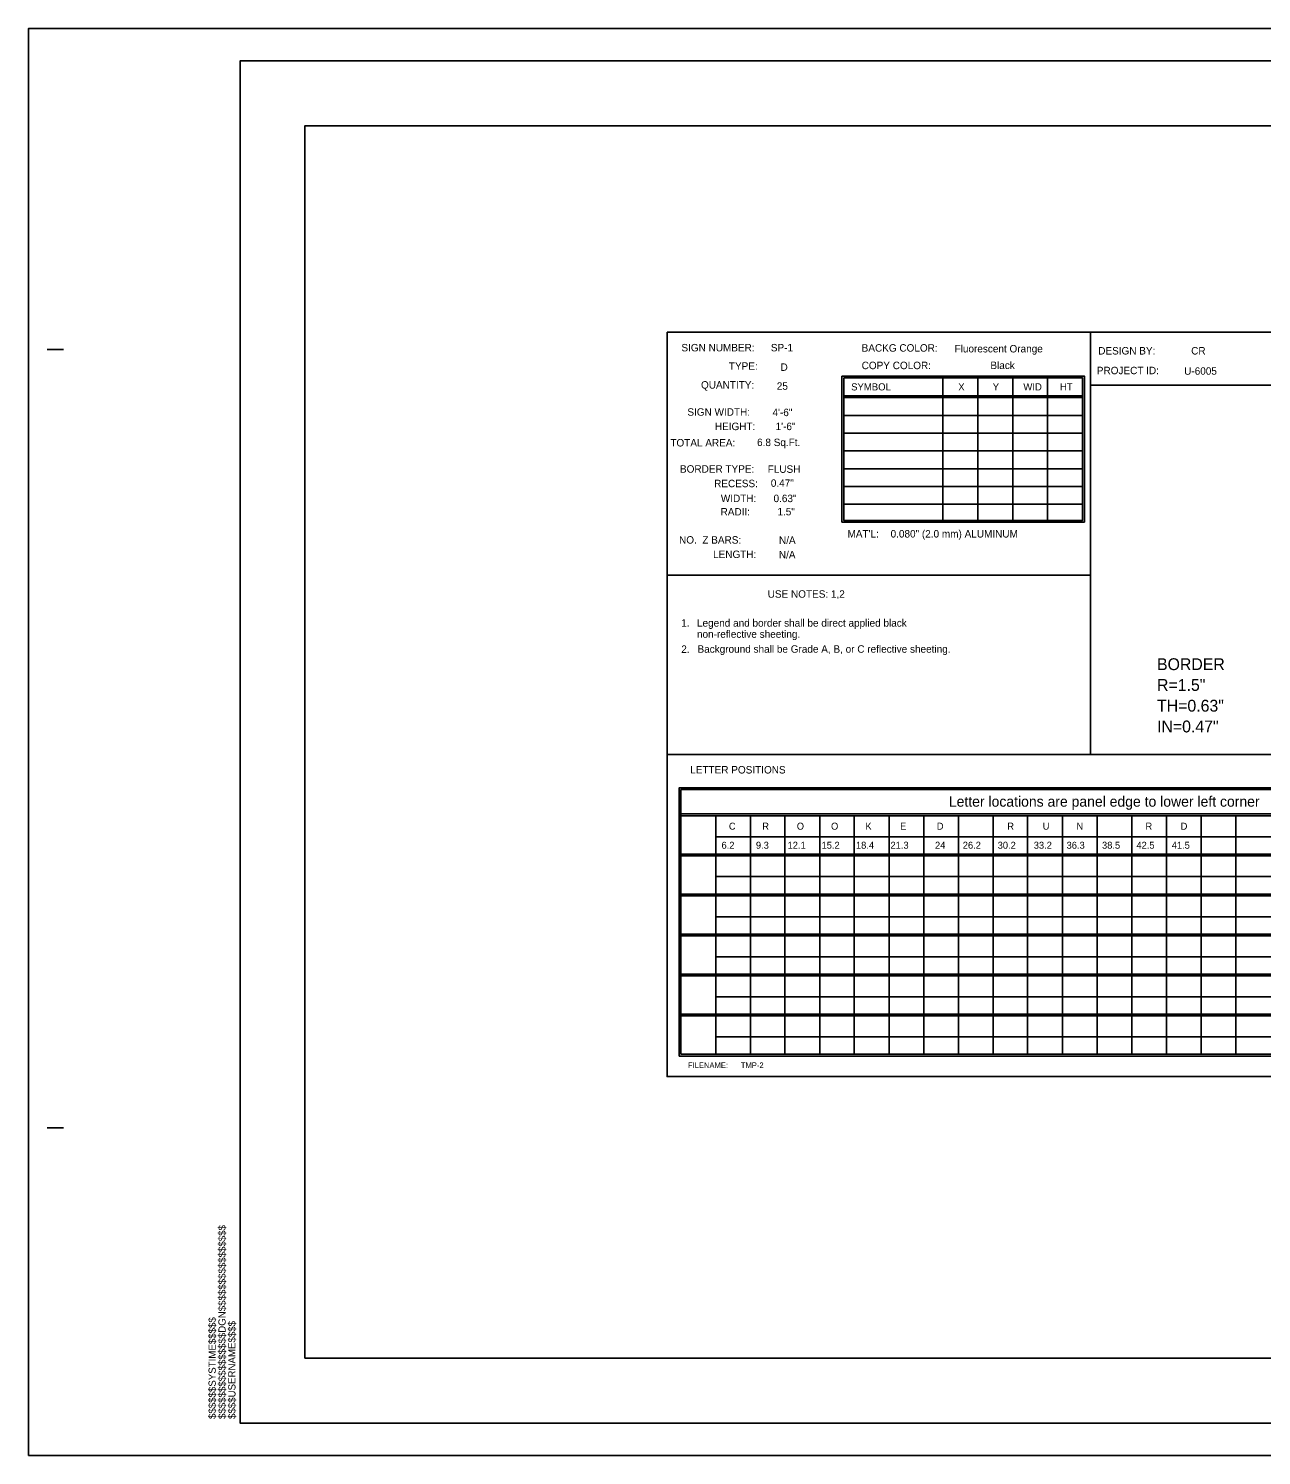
# Model space of a CAD drawing. Extents: x 768137 to 769825, y 651421 to 652521.
# Drawn here: x 768137 to 769087, y 651421 to 652521 of the extents above; entities that cross this region are included whole.
import ezdxf

# ---------------------------------------------------------------- set-up
doc = ezdxf.new("R2010")
doc.units = 0
for name, color, linetype in [('DEV BORDER CELL', 7, 'Continuous'), ('Old_Level_3', 7, 'Continuous'), ('Scratch_Level_0', 7, 'Continuous'), ('Sheet Plot Border Outside CELL', 7, 'Continuous'), ('Text', 7, 'Continuous')]:
    doc.layers.add(name, color=color, linetype=linetype)

msp = doc.modelspace()

# ---------------------------------------------------------------- linework, layer by layer
at = {"layer": 'DEV BORDER CELL'}
for p, q in [((768151.8, 652273.8), (768164.3, 652273.8)), ((768151.8, 651673.8), (768164.3, 651673.8))]:
    msp.add_line(p, q, dxfattribs=at)
msp.add_lwpolyline([(769800.3, 652496.3), (768300.3, 652496.3), (768300.3, 651446.3), (769800.3, 651446.3)], close=True, dxfattribs=at)
at = {"layer": 'Scratch_Level_0'}
msp.add_lwpolyline([(769750.3, 652446.3), (768350.3, 652446.3), (768350.3, 651496.3), (769229.2, 651496.3), (769229.2, 651614.6), (769750.3, 651614.6)], close=True, dxfattribs=at)
at = {"layer": 'Sheet Plot Border Outside CELL'}
msp.add_lwpolyline([(768137.3, 651421.3), (769825.3, 651421.3), (769825.3, 652521.3), (768137.3, 652521.3)], close=True, dxfattribs=at)
at = {"layer": 'Text'}
for p, q in [((768955.5, 652287.3), (768955.5, 651961.7)), ((768841.9, 652251.9), (768841.9, 652142.1)), ((768868.8, 652251.9), (768868.8, 652142.1)), ((768895.7, 652251.9), (768895.7, 652142.1)), ((768922.6, 652251.9), (768922.6, 652142.1)), ((768955.5, 652246.4), (769457, 652246.4)), ((768765.5, 652238.2), (768949.5, 652238.2)), ((768765.5, 652236.9), (768949.5, 652236.9)), ((768765.5, 652223.1), (768949.5, 652223.1)), ((768765.5, 652209.4), (768949.5, 652209.4)), ((768765.5, 652195.7), (768949.5, 652195.7)), ((768765.5, 652181.9), (768949.5, 652181.9)), ((768765.5, 652168.2), (768949.5, 652168.2)), ((768765.5, 652154.5), (768949.5, 652154.5)), ((768955.5, 652099.8), (768629.3, 652099.8)), ((768629.3, 651961.7), (768955.5, 651961.7)), ((768955.5, 651961.7), (769457, 651961.7)), ((768640, 651915.8), (769276.3, 651915.8)), ((768640, 651914.4), (769276.3, 651914.4)), ((768666.8, 651914.4), (768666.8, 651884.9)), ((768693.6, 651914.4), (768693.6, 651884.9)), ((768720.2, 651914.4), (768720.2, 651884.9)), ((768747, 651914.4), (768747, 651884.9)), ((768773.6, 651914.4), (768773.6, 651884.9)), ((768800.4, 651914.4), (768800.4, 651884.9)), ((768827.2, 651914.4), (768827.2, 651884.9)), ((768853.8, 651914.4), (768853.8, 651884.9)), ((768880.6, 651914.4), (768880.6, 651884.9)), ((768907.2, 651914.4), (768907.2, 651884.9)), ((768934, 651914.4), (768934, 651884.9)), ((768960.8, 651914.4), (768960.8, 651884.9)), ((768987.4, 651914.4), (768987.4, 651884.9)), ((769014.2, 651914.4), (769014.2, 651884.9)), ((769040.8, 651914.4), (769040.8, 651884.9)), ((769067.6, 651914.4), (769067.6, 651884.9)), ((768666.8, 651898.3), (769276.3, 651898.3)), ((768640, 651884.9), (769276.3, 651884.9)), ((768640, 651883.6), (769276.3, 651883.6)), ((768666.8, 651883.6), (768666.8, 651854.1)), ((768693.6, 651883.6), (768693.6, 651854.1)), ((768720.2, 651883.6), (768720.2, 651854.1)), ((768747, 651883.6), (768747, 651854.1)), ((768773.6, 651883.6), (768773.6, 651854.1)), ((768800.4, 651883.6), (768800.4, 651854.1)), ((768827.2, 651883.6), (768827.2, 651854.1)), ((768853.8, 651883.6), (768853.8, 651854.1)), ((768880.6, 651883.6), (768880.6, 651854.1)), ((768907.2, 651883.6), (768907.2, 651854.1)), ((768934, 651883.6), (768934, 651854.1)), ((768960.8, 651883.6), (768960.8, 651854.1)), ((768987.4, 651883.6), (768987.4, 651854.1)), ((769014.2, 651883.6), (769014.2, 651854.1)), ((769040.8, 651883.6), (769040.8, 651854.1)), ((769067.6, 651883.6), (769067.6, 651854.1)), ((768666.8, 651867.5), (769276.3, 651867.5)), ((768640, 651854.1), (769276.3, 651854.1)), ((768640, 651852.7), (769276.3, 651852.7)), ((768666.8, 651852.7), (768666.8, 651823.2)), ((768693.6, 651852.7), (768693.6, 651823.2)), ((768720.2, 651852.7), (768720.2, 651823.2)), ((768747, 651852.7), (768747, 651823.2)), ((768773.6, 651852.7), (768773.6, 651823.2)), ((768800.4, 651852.7), (768800.4, 651823.2)), ((768827.2, 651852.7), (768827.2, 651823.2)), ((768853.8, 651852.7), (768853.8, 651823.2)), ((768880.6, 651852.7), (768880.6, 651823.2)), ((768907.2, 651852.7), (768907.2, 651823.2)), ((768934, 651852.7), (768934, 651823.2)), ((768960.8, 651852.7), (768960.8, 651823.2)), ((768987.4, 651852.7), (768987.4, 651823.2)), ((769014.2, 651852.7), (769014.2, 651823.2)), ((769040.8, 651852.7), (769040.8, 651823.2)), ((769067.6, 651852.7), (769067.6, 651823.2)), ((768666.8, 651836.6), (769276.3, 651836.6)), ((768640, 651823.2), (769276.3, 651823.2)), ((768640, 651821.8), (769276.3, 651821.8)), ((768666.8, 651821.8), (768666.8, 651792.3)), ((768693.6, 651821.8), (768693.6, 651792.3)), ((768720.2, 651821.8), (768720.2, 651792.3)), ((768747, 651821.8), (768747, 651792.3)), ((768773.6, 651821.8), (768773.6, 651792.3)), ((768800.4, 651821.8), (768800.4, 651792.3)), ((768827.2, 651821.8), (768827.2, 651792.3)), ((768853.8, 651821.8), (768853.8, 651792.3)), ((768880.6, 651821.8), (768880.6, 651792.3)), ((768907.2, 651821.8), (768907.2, 651792.3)), ((768934, 651821.8), (768934, 651792.3)), ((768960.8, 651821.8), (768960.8, 651792.3)), ((768987.4, 651821.8), (768987.4, 651792.3)), ((769014.2, 651821.8), (769014.2, 651792.3)), ((769040.8, 651821.8), (769040.8, 651792.3)), ((769067.6, 651821.8), (769067.6, 651792.3)), ((768666.8, 651805.7), (769276.3, 651805.7)), ((768666.8, 651795.8), (768666.8, 651792.3)), ((768693.6, 651795.8), (768693.6, 651792.3)), ((768720.2, 651795.8), (768720.2, 651792.3)), ((768747, 651795.8), (768747, 651792.3)), ((768773.6, 651795.8), (768773.6, 651792.3)), ((768800.4, 651795.8), (768800.4, 651792.3)), ((768827.2, 651795.8), (768827.2, 651792.3)), ((768853.8, 651795.8), (768853.8, 651792.3)), ((768880.6, 651795.8), (768880.6, 651792.3)), ((768907.2, 651795.8), (768907.2, 651792.3)), ((768934, 651795.8), (768934, 651792.3)), ((768960.8, 651795.8), (768960.8, 651792.3)), ((768987.4, 651795.8), (768987.4, 651792.3)), ((769014.2, 651795.8), (769014.2, 651792.3)), ((769040.8, 651795.8), (769040.8, 651792.3)), ((769067.6, 651795.8), (769067.6, 651792.3)), ((768640, 651792.3), (769276.3, 651792.3)), ((768640, 651792.3), (769276.3, 651792.3)), ((768640, 651791), (769276.3, 651791)), ((768640, 651791), (769276.3, 651791)), ((768666.8, 651791), (768666.8, 651763.4)), ((768666.8, 651791), (768666.8, 651761.5)), ((768693.6, 651791), (768693.6, 651763.4)), ((768693.6, 651791), (768693.6, 651761.5)), ((768720.2, 651791), (768720.2, 651763.4)), ((768720.2, 651791), (768720.2, 651761.5)), ((768747, 651791), (768747, 651763.4)), ((768747, 651791), (768747, 651761.5)), ((768773.6, 651791), (768773.6, 651763.4)), ((768773.6, 651791), (768773.6, 651761.5)), ((768800.4, 651791), (768800.4, 651763.4)), ((768800.4, 651791), (768800.4, 651761.5)), ((768827.2, 651791), (768827.2, 651763.4)), ((768827.2, 651791), (768827.2, 651761.5)), ((768853.8, 651791), (768853.8, 651763.4)), ((768853.8, 651791), (768853.8, 651761.5)), ((768880.6, 651791), (768880.6, 651763.4)), ((768880.6, 651791), (768880.6, 651761.5)), ((768907.2, 651791), (768907.2, 651763.4)), ((768907.2, 651791), (768907.2, 651761.5)), ((768934, 651791), (768934, 651763.4)), ((768934, 651791), (768934, 651761.5)), ((768960.8, 651791), (768960.8, 651763.4)), ((768960.8, 651791), (768960.8, 651761.5)), ((768987.4, 651791), (768987.4, 651763.4)), ((768987.4, 651791), (768987.4, 651761.5)), ((769014.2, 651791), (769014.2, 651763.4)), ((769014.2, 651791), (769014.2, 651761.5)), ((769040.8, 651791), (769040.8, 651763.4)), ((769040.8, 651791), (769040.8, 651761.5)), ((769067.6, 651791), (769067.6, 651763.4)), ((769067.6, 651791), (769067.6, 651761.5)), ((768666.8, 651774.9), (769276.3, 651774.9)), ((768666.8, 651774.9), (769276.3, 651774.9)), ((768640, 651761.5), (769276.3, 651761.5)), ((768640, 651761.5), (769276.3, 651761.5)), ((768666.8, 651764.9), (768666.8, 651761.5)), ((768693.6, 651764.9), (768693.6, 651761.5)), ((768720.2, 651764.9), (768720.2, 651761.5)), ((768747, 651764.9), (768747, 651761.5)), ((768773.6, 651764.9), (768773.6, 651761.5)), ((768800.4, 651764.9), (768800.4, 651761.5)), ((768827.2, 651764.9), (768827.2, 651761.5)), ((768853.8, 651764.9), (768853.8, 651761.5)), ((768880.6, 651764.9), (768880.6, 651761.5)), ((768907.2, 651764.9), (768907.2, 651761.5)), ((768934, 651764.9), (768934, 651761.5)), ((768960.8, 651764.9), (768960.8, 651761.5)), ((768987.4, 651764.9), (768987.4, 651761.5)), ((769014.2, 651764.9), (769014.2, 651761.5)), ((769040.8, 651764.9), (769040.8, 651761.5)), ((769067.6, 651764.9), (769067.6, 651761.5)), ((768640, 651760.1), (769276.3, 651760.1)), ((768640, 651760.1), (769276.3, 651760.1)), ((768666.8, 651760.1), (768666.8, 651730.6)), ((768666.8, 651760.1), (768666.8, 651730.6)), ((768693.6, 651760.1), (768693.6, 651730.6)), ((768693.6, 651760.1), (768693.6, 651730.6)), ((768720.2, 651760.1), (768720.2, 651730.6)), ((768720.2, 651760.1), (768720.2, 651730.6)), ((768747, 651760.1), (768747, 651730.6)), ((768747, 651760.1), (768747, 651730.6)), ((768773.6, 651760.1), (768773.6, 651730.6)), ((768773.6, 651760.1), (768773.6, 651730.6)), ((768800.4, 651760.1), (768800.4, 651730.6)), ((768800.4, 651760.1), (768800.4, 651730.6)), ((768827.2, 651760.1), (768827.2, 651730.6)), ((768827.2, 651760.1), (768827.2, 651730.6)), ((768853.8, 651760.1), (768853.8, 651730.6)), ((768853.8, 651760.1), (768853.8, 651730.6)), ((768880.6, 651760.1), (768880.6, 651730.6)), ((768880.6, 651760.1), (768880.6, 651730.6)), ((768907.2, 651760.1), (768907.2, 651730.6)), ((768907.2, 651760.1), (768907.2, 651730.6)), ((768934, 651760.1), (768934, 651730.6)), ((768934, 651760.1), (768934, 651730.6)), ((768960.8, 651760.1), (768960.8, 651730.6)), ((768960.8, 651760.1), (768960.8, 651730.6)), ((768987.4, 651760.1), (768987.4, 651730.6)), ((768987.4, 651760.1), (768987.4, 651730.6)), ((769014.2, 651760.1), (769014.2, 651730.6)), ((769014.2, 651760.1), (769014.2, 651730.6)), ((769040.8, 651760.1), (769040.8, 651730.6)), ((769040.8, 651760.1), (769040.8, 651730.6)), ((769067.6, 651760.1), (769067.6, 651730.6)), ((769067.6, 651760.1), (769067.6, 651730.6)), ((768666.8, 651744), (769276.3, 651744)), ((768666.8, 651744), (769276.3, 651744)), ((768638.6, 651729.2), (769276.3, 651729.2)), ((768640, 651730.6), (769276.3, 651730.6)), ((768640, 651730.6), (769276.3, 651730.6)), ((768640, 651729.2), (769276.3, 651729.2))]:
    msp.add_line(p, q, dxfattribs=at)
for points in [[(768629.3, 652287.3), (769457, 652287.3), (769457, 651713.3), (768629.3, 651713.3)], [(768764.1, 652253.3), (768950.9, 652253.3), (768950.9, 652140.8), (768764.1, 652140.8)], [(768765.5, 652251.9), (768949.5, 652251.9), (768949.5, 652142.1), (768765.5, 652142.1)]]:
    msp.add_lwpolyline(points, close=True, dxfattribs=at)
for points in [[(768638.6, 651763.4), (768638.6, 651935.9), (769276.3, 651935.9)], [(768640, 651763.4), (768640, 651934.6), (769276.3, 651934.6)], [(768638.6, 651729.2), (768638.6, 651795.8)], [(768640, 651730.6), (768640, 651795.8)]]:
    msp.add_lwpolyline(points, dxfattribs=at)

# ---------------------------------------------------------------- texts
at = {"layer": 'DEV BORDER CELL'}
for s, p in [('$$$$$$$$$$$$$$$$DGN$$$$$$$$$$$$$$$$', (768289.2, 651449.4)), ('$$$$$$SYSTIME$$$$$', (768281.6, 651449.4)), ('$$$$USERNAME$$$$', (768296.8, 651449.4))]:
    msp.add_text(s, height=5.584, rotation=90, dxfattribs=at).set_placement(p)
at = {"layer": 'Old_Level_3'}
for s, height, p in [('SP-1', 5.75, (768709.3, 652272.4)), ('Fluorescent Orange', 5.752, (768850.9, 652271.6)), ('D', 5.75, (768716.8, 652257.4)), ('25', 5.75, (768713.9, 652242.8)), ('4\'-6"', 5.75, (768710.6, 652222.5)), ('1\'-6"', 5.75, (768713, 652211.7)), ('6.8 Sq.Ft.', 5.75, (768698.7, 652199.4)), ('FLUSH', 5.75, (768706.9, 652178.8)), ('0.47"', 5.75, (768709.3, 652168)), ('0.63"', 5.75, (768711.4, 652156.2)), ('1.5"', 5.75, (768714.4, 652146)), ('N/A', 5.75, (768715.6, 652124)), ('N/A', 5.75, (768715.5, 652112.8))]:
    msp.add_text(s, height=height, rotation=360, dxfattribs=at).set_placement(p)
msp.add_text('Black', height=5.75, dxfattribs=at).set_placement((768878.5, 652258.8))
at = {"layer": 'Text'}
for s, height, p in [('SIGN NUMBER:', 5.752, (768640.4, 652272.4)), ('BACKG COLOR:', 5.752, (768779.3, 652272.2)), ('DESIGN BY:', 5.75, (768961.6, 652270)), ('CR', 5.75, (769033.2, 652270)), ('TYPE:', 5.75, (768677, 652258.2)), ('COPY COLOR:', 5.752, (768779.3, 652258.7)), ('PROJECT ID:', 5.752, (768960.5, 652254.8)), ('U-6005', 5.75, (769027.8, 652254.4)), ('QUANTITY:', 5.75, (768655.5, 652243.7)), ('SIGN WIDTH:', 5.752, (768645, 652222.8)), ('HEIGHT:', 5.75, (768666.2, 652211.7)), ('TOTAL AREA:', 5.752, (768631.9, 652199.1)), ('BORDER TYPE:', 5.752, (768639.3, 652178.9)), ('RECESS:', 5.75, (768665.6, 652167.7)), ('WIDTH:', 5.75, (768670.8, 652156.2)), ('RADII:', 5.75, (768670.6, 652145.9)), ('NO.  Z BARS:', 5.752, (768638.6, 652124.2)), ("MAT'L:", 5.75, (768768.4, 652128.9)), ('LENGTH:', 5.75, (768664.8, 652113.1)), ('USE NOTES: 1,2', 5.752, (768706.9, 652082.5)), ('1.', 5.75, (768640.3, 652060.2)), ('Legend and border shall be direct applied black      ', 5.752, (768652.4, 652060.2)), ('2.', 5.75, (768640.3, 652040)), ('LETTER POSITIONS', 5.752, (768647.2, 651947)), ('Letter locations are panel edge to lower left corner', 8.052, (768846.5, 651921.4)), ('FILENAME:', 4.38, (768645.4, 651719.9)), ('TMP-2', 4.38, (768686.2, 651719.9))]:
    msp.add_text(s, height=height, rotation=360, dxfattribs=at).set_placement(p)
for s, height, p in [('SYMBOL', 5.49, (768771.2, 652242.3)), ('X', 5.49, (768853.7, 652242.3)), ('Y', 5.49, (768880.3, 652242.3)), ('WID', 5.49, (768903.9, 652242.3)), ('HT', 5.49, (768932.1, 652242.3)), ('0.080" (2.0 mm) ALUMINUM', 5.752, (768801.6, 652128.9)), ('non-reflective sheeting.', 5.752, (768652.4, 652051.6)), ('Background shall be Grade A, B, or C reflective sheeting.', 5.752, (768652.8, 652040.1)), ('BORDER', 9.13, (769006.9, 652026.7)), ('R=1.5"', 9.13, (769006.9, 652010.7)), ('TH=0.63"', 9.13, (769006.9, 651994.7)), ('IN=0.47"', 9.13, (769006.9, 651978.7)), ('C', 5.37, (768677, 651903.7)), ('R', 5.37, (768702.7, 651903.7)), ('O', 5.37, (768729.3, 651903.7)), ('O', 5.37, (768755.7, 651903.7)), ('K', 5.37, (768782.2, 651903.7)), ('E', 5.37, (768808.9, 651903.7)), ('D', 5.37, (768837.2, 651903.7)), ('R', 5.37, (768891.5, 651903.7)), ('U', 5.37, (768918.8, 651903.7)), ('N', 5.37, (768944.8, 651903.7)), ('R', 5.37, (768998, 651903.7)), ('D', 5.37, (769025.1, 651903.7)), ('6.2', 5.37, (768671.3, 651889)), ('9.3', 5.37, (768697.8, 651889)), ('12.1', 5.37, (768722.2, 651889)), ('15.2', 5.37, (768748.4, 651889)), ('18.4', 5.37, (768774.9, 651889)), ('21.3', 5.37, (768801.5, 651889)), ('24', 5.37, (768835.8, 651889)), ('26.2', 5.37, (768857.2, 651889)), ('30.2', 5.37, (768884.1, 651889)), ('33.2', 5.37, (768911.9, 651889)), ('36.3', 5.37, (768937.2, 651889)), ('38.5', 5.37, (768964.5, 651889)), ('42.5', 5.37, (768991, 651889)), ('41.5', 5.37, (769018.2, 651889))]:
    msp.add_text(s, height=height, dxfattribs=at).set_placement(p)

doc.saveas('drawing.dxf')
